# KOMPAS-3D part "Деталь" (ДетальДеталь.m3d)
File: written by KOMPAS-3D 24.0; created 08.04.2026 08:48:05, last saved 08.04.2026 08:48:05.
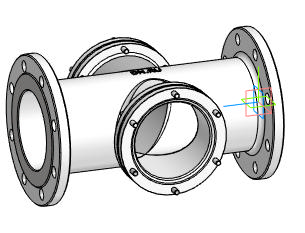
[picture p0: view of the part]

Document properties: Автор: Main; Полное имя файла: D:\DN.ru Аутсерс\Стекло смотровое DN.ru\Исходники\Стекло смотровое DN.ru SG2-34G-F тип В ГОСТ 21836-2021 Ду150 Ру16, углеродистая сталь, фланцевое\ДетальДеталь.m3d

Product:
- Body: Твердое тело1  | qty 1
- Part/product: Деталь
    additional columns: Типовые

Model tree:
1. Твердое тело1  (labels: Твердое тело1)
